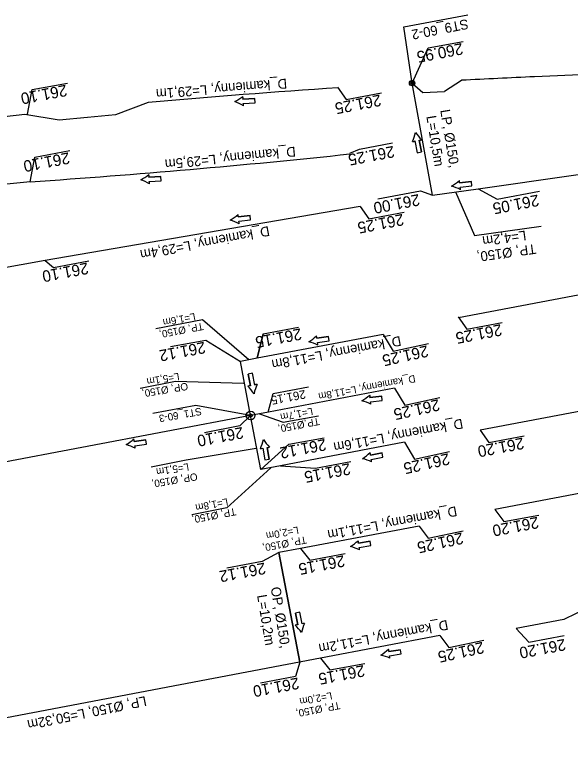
# Model space of a CAD drawing. Extents: x -1 to 65640748, y -22 to 5530284.
# Drawn here: x 6558158.5 to 6558209.5, y 5528782.8 to 5528851.6 of the extents above; entities that cross this region are included whole.
import ezdxf

# ---------------------------------------------------------------- set-up
doc = ezdxf.new("R2010")
doc.units = 0
for name, color, linetype in [('TOR_PROF-studnie i osadniki', 7, 'Continuous'), ('TOR_PS_ODW-drenaze', 7, 'Continuous'), ('TOR_PS_ODW-drenokolektory', 7, 'Continuous'), ('TOR_PS_ODW-kolektory', 7, 'Continuous'), ('TOR_PS_ODW-studnie PEHD', 7, 'Continuous'), ('TOR_PS_OPIS_O-opisy rurociagow', 7, 'Continuous'), ('TOR_PS_OPIS_O-opisy studni', 7, 'Continuous'), ('TOR_PS_OPIS_T-INFO', 7, 'Continuous')]:
    doc.layers.add(name, color=color, linetype=linetype)

msp = doc.modelspace()

# ---------------------------------------------------------------- linework, layer by layer
at = {"layer": 'TOR_PROF-studnie i osadniki'}
for radius in [0.25, 0.125]:
    msp.add_circle((6558194.96, 5528845.381), radius, dxfattribs=at)
at = {"layer": 'TOR_PS_ODW-drenaze'}
for p, q in [((6558170.712, 5528843.594), (6558167.708, 5528842.472)), ((6558162.532, 5528841.974), (6558159.37, 5528842.504)), ((6558165.12, 5528842.223), (6558162.532, 5528841.974)), ((6558167.708, 5528842.472), (6558165.12, 5528842.223)), ((6558192.306, 5528822.298), (6558180.732, 5528820.104)), ((6558240.436, 5528820.938), (6558201.211, 5528813.503)), ((6558193.352, 5528817.357), (6558181.748, 5528815.157)), ((6558242.093, 5528813.721), (6558202.565, 5528806.228)), ((6558194.258, 5528812.389), (6558182.875, 5528810.231)), ((6558197.501, 5528794.632), (6558186.538, 5528792.554))]:
    msp.add_line(p, q, dxfattribs=at)
for points in [[(6558159.37, 5528842.504), (6558140.943, 5528840.386), (6558137.359, 5528840.849), (6558132.205, 5528840.156), (6558124.752, 5528838.168)], [(6558201.038, 5528835.683), (6558235.617, 5528840.624)], [(6558159.869, 5528836.318), (6558159.869, 5528836.318), (6558142.805, 5528834.603)], [(6558196.842, 5528835.084), (6558196.842, 5528835.084), (6558201.038, 5528835.683)], [(6558190.193, 5528834.047), (6558163.214, 5528829.433), (6558161.25, 5528829.08)], [(6558238.341, 5528831.228), (6558199.221, 5528823.813)], [(6558161.25, 5528829.08), (6558127.62, 5528823.039)], [(6558180.732, 5528820.104), (6558179.181, 5528819.811)], [(6558182.875, 5528810.231), (6558181.062, 5528809.887)], [(6558195.594, 5528804.703), (6558184.71, 5528802.64)], [(6558243.69, 5528803.387), (6558211.159, 5528797.221), (6558208.896, 5528796.13), (6558204.51, 5528795.299)], [(6558186.538, 5528792.554), (6558150.243, 5528785.674), (6558147.981, 5528784.584), (6558142.872, 5528783.615), (6558135.31, 5528782.843)]]:
    msp.add_lwpolyline(points, dxfattribs=at)
for centre, radius, start, end in [((6558241.925, 5528042.955), 803.8, 93.834266, 95.082808), ((6558109.688, 5529583.067), 748.433, 273.844417, 276.102336)]:
    msp.add_arc(centre, radius, start, end, dxfattribs=at)
at = {"layer": 'TOR_PS_ODW-drenokolektory'}
for p, q in [((6558235.052, 5528847.244), (6558206.197, 5528845.96)), ((6558199.496, 5528845.63), (6558197.947, 5528844.622)), ((6558194.96, 5528845.381), (6558195.939, 5528844.51)), ((6558195.939, 5528844.51), (6558197.947, 5528844.622)), ((6558180.732, 5528820.104), (6558179.181, 5528819.811)), ((6558180.122, 5528814.849), (6558130.962, 5528805.531)), ((6558181.748, 5528815.157), (6558180.122, 5528814.849)), ((6558182.875, 5528810.231), (6558181.062, 5528809.887))]:
    msp.add_line(p, q, dxfattribs=at)
for points in [[(6558196.842, 5528835.084), (6558194.96, 5528845.381)], [(6558184.71, 5528802.64), (6558182.719, 5528802.262)]]:
    msp.add_lwpolyline(points, dxfattribs=at)
msp.add_arc((6558241.925, 5528042.955), 803.8, 92.547544, 93.025826, dxfattribs=at)
at = {"layer": 'TOR_PS_ODW-kolektory'}
for p, q in [((6558180.122, 5528814.849), (6558179.181, 5528819.811)), ((6558181.062, 5528809.887), (6558180.122, 5528814.849))]:
    msp.add_line(p, q, dxfattribs=at)
for points in [[(6558182.719, 5528802.262), (6558184.628, 5528792.192)], [(6558184.628, 5528792.192), (6558182.719, 5528802.262)]]:
    msp.add_lwpolyline(points, dxfattribs=at)
at = {"layer": 'TOR_PS_ODW-studnie PEHD'}
for centre, radius in [((6558194.96, 5528845.381), 0.25), ((6558194.96, 5528845.381), 0.112), ((6558180.122, 5528814.849), 0.4), ((6558180.122, 5528814.849), 0.145)]:
    msp.add_circle(centre, radius, dxfattribs=at)
at = {"layer": 'TOR_PS_OPIS_O-opisy rurociagow'}
for p, q in [((6558180.505, 5528843.974), (6558179.414, 5528843.916)), ((6558179.414, 5528843.916), (6558180.505, 5528843.974)), ((6558179.435, 5528843.517), (6558180.527, 5528843.575)), ((6558179.435, 5528843.517), (6558180.527, 5528843.575)), ((6558180.527, 5528843.575), (6558180.505, 5528843.974)), ((6558180.527, 5528843.575), (6558180.505, 5528843.974)), ((6558195.814, 5528839.063), (6558195.611, 5528840.136)), ((6558195.611, 5528840.136), (6558195.814, 5528839.063)), ((6558195.218, 5528840.062), (6558195.421, 5528838.988)), ((6558195.218, 5528840.062), (6558195.421, 5528838.988)), ((6558195.421, 5528838.988), (6558195.814, 5528839.063)), ((6558195.421, 5528838.988), (6558195.814, 5528839.063)), ((6558171.874, 5528836.806), (6558170.783, 5528836.747)), ((6558170.783, 5528836.747), (6558171.874, 5528836.806)), ((6558171.895, 5528836.406), (6558171.874, 5528836.806)), ((6558171.895, 5528836.406), (6558171.874, 5528836.806)), ((6558170.804, 5528836.348), (6558171.895, 5528836.406)), ((6558170.804, 5528836.348), (6558171.895, 5528836.406)), ((6558200.404, 5528836.35), (6558199.321, 5528836.209)), ((6558199.321, 5528836.209), (6558200.404, 5528836.35)), ((6558199.373, 5528835.812), (6558200.456, 5528835.954)), ((6558199.373, 5528835.812), (6558200.456, 5528835.954)), ((6558200.456, 5528835.954), (6558200.404, 5528836.35)), ((6558200.456, 5528835.954), (6558200.404, 5528836.35)), ((6558180.069, 5528833.226), (6558178.985, 5528833.084)), ((6558178.985, 5528833.084), (6558180.069, 5528833.226)), ((6558180.12, 5528832.829), (6558180.069, 5528833.226)), ((6558180.12, 5528832.829), (6558180.069, 5528833.226)), ((6558179.037, 5528832.688), (6558180.12, 5528832.829)), ((6558179.037, 5528832.688), (6558180.12, 5528832.829)), ((6558187.267, 5528822.118), (6558186.189, 5528821.939)), ((6558186.189, 5528821.939), (6558187.267, 5528822.118)), ((6558186.255, 5528821.545), (6558187.333, 5528821.723)), ((6558186.255, 5528821.545), (6558187.333, 5528821.723)), ((6558187.333, 5528821.723), (6558187.267, 5528822.118)), ((6558187.333, 5528821.723), (6558187.267, 5528822.118)), ((6558180.293, 5528818.726), (6558179.899, 5528818.653)), ((6558180.293, 5528818.726), (6558179.899, 5528818.653)), ((6558179.899, 5528818.653), (6558180.099, 5528817.579)), ((6558180.099, 5528817.579), (6558179.899, 5528818.653)), ((6558180.492, 5528817.652), (6558180.293, 5528818.726)), ((6558180.492, 5528817.652), (6558180.293, 5528818.726)), ((6558192.169, 5528816.641), (6558191.085, 5528816.504)), ((6558191.085, 5528816.504), (6558192.169, 5528816.641)), ((6558191.135, 5528816.107), (6558192.219, 5528816.244)), ((6558191.135, 5528816.107), (6558192.219, 5528816.244)), ((6558192.219, 5528816.244), (6558192.169, 5528816.641)), ((6558192.219, 5528816.244), (6558192.169, 5528816.641)), ((6558170.504, 5528812.609), (6558169.42, 5528812.472)), ((6558169.42, 5528812.472), (6558170.504, 5528812.609)), ((6558170.554, 5528812.212), (6558170.504, 5528812.609)), ((6558170.554, 5528812.212), (6558170.504, 5528812.609)), ((6558169.47, 5528812.075), (6558170.554, 5528812.212)), ((6558169.47, 5528812.075), (6558170.554, 5528812.212)), ((6558181.829, 5528810.847), (6558181.629, 5528811.921)), ((6558181.629, 5528811.921), (6558181.829, 5528810.847)), ((6558181.236, 5528811.848), (6558181.436, 5528810.774)), ((6558181.236, 5528811.848), (6558181.436, 5528810.774)), ((6558192.195, 5528811.409), (6558191.12, 5528811.217)), ((6558191.12, 5528811.217), (6558192.195, 5528811.409)), ((6558192.266, 5528811.015), (6558192.195, 5528811.409)), ((6558192.266, 5528811.015), (6558192.195, 5528811.409)), ((6558181.436, 5528810.774), (6558181.829, 5528810.847)), ((6558181.436, 5528810.774), (6558181.829, 5528810.847)), ((6558191.19, 5528810.823), (6558192.266, 5528811.015)), ((6558191.19, 5528810.823), (6558192.266, 5528811.015)), ((6558191.095, 5528803.304), (6558190.016, 5528803.131)), ((6558190.016, 5528803.131), (6558191.095, 5528803.304)), ((6558191.158, 5528802.909), (6558191.095, 5528803.304)), ((6558191.158, 5528802.909), (6558191.095, 5528803.304)), ((6558190.079, 5528802.736), (6558191.158, 5528802.909)), ((6558190.079, 5528802.736), (6558191.158, 5528802.909)), ((6558184.645, 5528796.78), (6558184.251, 5528796.707)), ((6558184.645, 5528796.78), (6558184.251, 5528796.707)), ((6558184.844, 5528795.705), (6558184.645, 5528796.78)), ((6558184.844, 5528795.705), (6558184.645, 5528796.78)), ((6558184.251, 5528796.707), (6558184.451, 5528795.632)), ((6558184.451, 5528795.632), (6558184.251, 5528796.707)), ((6558193.886, 5528793.345), (6558192.807, 5528793.172)), ((6558192.807, 5528793.172), (6558193.886, 5528793.345)), ((6558193.949, 5528792.95), (6558193.886, 5528793.345)), ((6558193.949, 5528792.95), (6558193.886, 5528793.345)), ((6558192.87, 5528792.777), (6558193.949, 5528792.95)), ((6558192.87, 5528792.777), (6558193.949, 5528792.95))]:
    msp.add_line(p, q, dxfattribs=at)
for points in [[(6558179.412, 5528844.141), (6558179.412, 5528844.141)], [(6558179.458, 5528843.293), (6558179.458, 5528843.293)], [(6558195.834, 5528840.168), (6558195.834, 5528840.168)], [(6558194.999, 5528840.01), (6558194.999, 5528840.01)], [(6558170.781, 5528836.972), (6558170.781, 5528836.972)], [(6558170.826, 5528836.124), (6558170.826, 5528836.124)], [(6558199.302, 5528836.433), (6558199.302, 5528836.433)], [(6558199.412, 5528835.591), (6558199.412, 5528835.591)], [(6558178.966, 5528833.309), (6558178.966, 5528833.309)], [(6558179.076, 5528832.466), (6558179.076, 5528832.466)], [(6558186.163, 5528822.163), (6558186.163, 5528822.163)], [(6558186.302, 5528821.324), (6558186.302, 5528821.325)], [(6558179.876, 5528817.548), (6558179.876, 5528817.548)], [(6558180.711, 5528817.703), (6558180.711, 5528817.703)], [(6558191.067, 5528816.729), (6558191.067, 5528816.729)], [(6558191.173, 5528815.886), (6558191.173, 5528815.886)], [(6558169.402, 5528812.696), (6558169.402, 5528812.696)], [(6558181.852, 5528811.952), (6558181.852, 5528811.952)], [(6558169.509, 5528811.853), (6558169.509, 5528811.853)], [(6558181.017, 5528811.797), (6558181.017, 5528811.797)], [(6558191.09, 5528811.44), (6558191.09, 5528811.44)], [(6558191.239, 5528810.604), (6558191.239, 5528810.604)], [(6558189.99, 5528803.355), (6558189.99, 5528803.355)], [(6558190.125, 5528802.516), (6558190.125, 5528802.516)], [(6558184.228, 5528795.601), (6558184.228, 5528795.601)], [(6558185.063, 5528795.757), (6558185.063, 5528795.757)], [(6558192.782, 5528793.396), (6558192.782, 5528793.396)], [(6558192.916, 5528792.557), (6558192.916, 5528792.557)]]:
    msp.add_lwpolyline(points, dxfattribs=at)
for centre, radius, start, end in [((6558176.469, 5528848.081), 4.918, 296.3889, 306.77073), ((6558176.469, 5528848.081), 4.918, 296.3889, 306.77073), ((6558176.951, 5528839.062), 4.918, 59.35101, 69.73284), ((6558176.951, 5528839.062), 4.918, 59.35101, 69.73284), ((6558178.969, 5528844.025), 0.458, 346.19493, 14.65617), ((6558178.969, 5528844.025), 0.458, 346.19493, 14.65617), ((6558179.005, 5528843.361), 0.458, 351.46558, 19.92682), ((6558179.005, 5528843.361), 0.458, 351.46558, 19.92682), ((6558190.471, 5528841.93), 4.918, 337.02338, 347.40521), ((6558190.471, 5528841.93), 4.918, 337.02338, 347.40521), ((6558199.345, 5528843.612), 4.918, 214.06127, 224.4431), ((6558199.345, 5528843.612), 4.918, 214.06127, 224.4431), ((6558195.66, 5528840.592), 0.458, 263.86729, 292.32853), ((6558195.66, 5528840.592), 0.458, 263.86729, 292.32853), ((6558195.006, 5528840.468), 0.458, 269.13794, 297.59919), ((6558195.006, 5528840.468), 0.458, 269.13794, 297.59919), ((6558167.837, 5528840.912), 4.918, 296.3889, 306.77073), ((6558167.837, 5528840.912), 4.918, 296.3889, 306.77073), ((6558170.338, 5528836.856), 0.458, 346.19493, 14.65617), ((6558170.338, 5528836.856), 0.458, 346.19493, 14.65617), ((6558168.319, 5528831.893), 4.918, 59.35101, 69.73284), ((6558168.319, 5528831.893), 4.918, 59.35101, 69.73284), ((6558170.374, 5528836.192), 0.458, 351.46558, 19.92682), ((6558170.374, 5528836.192), 0.458, 351.46558, 19.92682), ((6558196.066, 5528840.137), 4.918, 300.76623, 311.14806), ((6558196.066, 5528840.137), 4.918, 300.76623, 311.14806), ((6558198.869, 5528836.284), 0.458, 350.57226, 19.0335), ((6558198.869, 5528836.284), 0.458, 350.57226, 19.0335), ((6558197.235, 5528831.181), 4.918, 63.72835, 74.11017), ((6558197.235, 5528831.181), 4.918, 63.72835, 74.11017), ((6558198.955, 5528835.624), 0.458, 355.84291, 24.30415), ((6558198.955, 5528835.624), 0.458, 355.84291, 24.30415), ((6558175.73, 5528837.012), 4.918, 300.76623, 311.14806), ((6558175.73, 5528837.012), 4.918, 300.76623, 311.14806), ((6558178.533, 5528833.159), 0.458, 350.57226, 19.0335), ((6558178.533, 5528833.159), 0.458, 350.57226, 19.0335), ((6558176.899, 5528828.056), 4.918, 63.72835, 74.11017), ((6558176.899, 5528828.056), 4.918, 63.72835, 74.11017), ((6558178.62, 5528832.499), 0.458, 355.84291, 24.30415), ((6558178.62, 5528832.499), 0.458, 355.84291, 24.30415), ((6558182.802, 5528825.753), 4.918, 302.72798, 313.10981), ((6558182.802, 5528825.753), 4.918, 302.72798, 313.10981), ((6558184.277, 5528816.843), 4.918, 65.69009, 76.07192), ((6558184.277, 5528816.843), 4.918, 65.69009, 76.07192), ((6558185.735, 5528821.999), 0.458, 352.534, 20.99524), ((6558185.735, 5528821.999), 0.458, 352.534, 20.99524), ((6558185.844, 5528821.342), 0.458, 357.80466, 26.2659), ((6558185.844, 5528821.342), 0.458, 357.80466, 26.2659), ((6558180.048, 5528817.124), 0.458, 83.66036, 112.1216), ((6558180.048, 5528817.124), 0.458, 83.66036, 112.1216), ((6558176.352, 5528814.117), 4.918, 33.85434, 44.23617), ((6558176.352, 5528814.117), 4.918, 33.85434, 44.23617), ((6558185.232, 5528815.767), 4.918, 156.81645, 167.19828), ((6558185.232, 5528815.767), 4.918, 156.81645, 167.19828), ((6558180.703, 5528817.245), 0.458, 88.93101, 117.39225), ((6558180.703, 5528817.245), 0.458, 88.93101, 117.39225), ((6558187.846, 5528820.445), 4.918, 300.53119, 310.91302), ((6558187.846, 5528820.445), 4.918, 300.53119, 310.91302), ((6558190.633, 5528816.581), 0.458, 350.33722, 18.79846), ((6558190.633, 5528816.581), 0.458, 350.33722, 18.79846), ((6558188.978, 5528811.485), 4.918, 63.4933, 73.87513), ((6558188.978, 5528811.485), 4.918, 63.4933, 73.87513), ((6558190.717, 5528815.921), 0.458, 355.60787, 24.06911), ((6558190.717, 5528815.921), 0.458, 355.60787, 24.06911), ((6558166.182, 5528816.413), 4.918, 300.53119, 310.91302), ((6558166.182, 5528816.413), 4.918, 300.53119, 310.91302), ((6558168.969, 5528812.549), 0.458, 350.33722, 18.79846), ((6558168.969, 5528812.549), 0.458, 350.33722, 18.79846), ((6558176.496, 5528813.733), 4.918, 336.81645, 347.19828), ((6558176.496, 5528813.733), 4.918, 336.81645, 347.19828), ((6558185.376, 5528815.383), 4.918, 213.85434, 224.23617), ((6558185.376, 5528815.383), 4.918, 213.85434, 224.23617), ((6558167.314, 5528807.453), 4.918, 63.4933, 73.87513), ((6558167.314, 5528807.453), 4.918, 63.4933, 73.87513), ((6558169.052, 5528811.889), 0.458, 355.60787, 24.06911), ((6558169.052, 5528811.889), 0.458, 355.60787, 24.06911), ((6558181.68, 5528812.376), 0.458, 263.66036, 292.1216), ((6558181.68, 5528812.376), 0.458, 263.66036, 292.1216), ((6558181.026, 5528812.254), 0.458, 268.93101, 297.39225), ((6558181.026, 5528812.254), 0.458, 268.93101, 297.39225), ((6558187.686, 5528814.989), 4.918, 303.42506, 313.80689), ((6558187.686, 5528814.989), 4.918, 303.42506, 313.80689), ((6558190.665, 5528811.271), 0.458, 353.23109, 21.69233), ((6558190.665, 5528811.271), 0.458, 353.23109, 21.69233), ((6558189.27, 5528806.098), 4.918, 66.38718, 76.769), ((6558189.27, 5528806.098), 4.918, 66.38718, 76.769), ((6558190.782, 5528810.616), 0.458, 358.50174, 26.96298), ((6558190.782, 5528810.616), 0.458, 358.50174, 26.96298), ((6558186.648, 5528806.962), 4.918, 302.43307, 312.81489), ((6558186.648, 5528806.962), 4.918, 302.43307, 312.81489), ((6558189.562, 5528803.193), 0.458, 352.23909, 20.70033), ((6558189.562, 5528803.193), 0.458, 352.23909, 20.70033), ((6558188.077, 5528798.044), 4.918, 65.39518, 75.77701), ((6558188.077, 5528798.044), 4.918, 65.39518, 75.77701), ((6558189.667, 5528802.536), 0.458, 357.50974, 25.97098), ((6558189.667, 5528802.536), 0.458, 357.50974, 25.97098), ((6558184.4, 5528795.177), 0.458, 83.66036, 112.1216), ((6558184.4, 5528795.177), 0.458, 83.66036, 112.1216), ((6558180.704, 5528792.171), 4.918, 33.85434, 44.23617), ((6558180.704, 5528792.171), 4.918, 33.85434, 44.23617), ((6558189.584, 5528793.821), 4.918, 156.81645, 167.19828), ((6558189.584, 5528793.821), 4.918, 156.81645, 167.19828), ((6558185.055, 5528795.299), 0.458, 88.93101, 117.39225), ((6558185.055, 5528795.299), 0.458, 88.93101, 117.39225), ((6558189.439, 5528797.003), 4.918, 302.43307, 312.81489), ((6558189.439, 5528797.003), 4.918, 302.43307, 312.81489), ((6558192.353, 5528793.234), 0.458, 352.23909, 20.70033), ((6558192.353, 5528793.234), 0.458, 352.23909, 20.70033), ((6558190.868, 5528788.085), 4.918, 65.39518, 75.77701), ((6558190.868, 5528788.085), 4.918, 65.39518, 75.77701), ((6558192.459, 5528792.576), 0.458, 357.50974, 25.97098), ((6558192.459, 5528792.576), 0.458, 357.50974, 25.97098)]:
    msp.add_arc(centre, radius, start, end, dxfattribs=at)
at = {"layer": 'TOR_PS_OPIS_T-INFO'}
for points in [[(6558194.96, 5528845.381), (6558194.189, 5528850.538), (6558200.083, 5528851.636)], [(6558194.96, 5528845.381), (6558196.418, 5528848.609), (6558199.655, 5528849.211)], [(6558159.625, 5528842.53), (6558160.044, 5528844.785), (6558163.281, 5528845.387)], [(6558188.092, 5528845.009), (6558188.901, 5528843.885), (6558192.138, 5528844.487)], [(6558189.243, 5528838.937), (6558190.136, 5528839.306), (6558193.145, 5528839.894)], [(6558159.869, 5528836.318), (6558160.288, 5528838.572), (6558163.525, 5528839.175)], [(6558191.809, 5528834.763), (6558191.809, 5528834.763), (6558195.716, 5528835.49), (6558196.842, 5528835.084)], [(6558198.94, 5528835.383), (6558200.687, 5528831.39), (6558206.814, 5528832.239)], [(6558201.038, 5528835.683), (6558202.758, 5528834.716), (6558206.666, 5528835.443)], [(6558190.171, 5528834.043), (6558190.98, 5528832.918), (6558194.217, 5528833.521)], [(6558161.25, 5528829.08), (6558162.012, 5528828.452), (6558165.249, 5528829.055)], [(6558179.956, 5528819.958), (6558175.702, 5528823.649), (6558171.417, 5528822.822)], [(6558199.183, 5528823.915), (6558199.991, 5528822.79), (6558203.229, 5528823.393)], [(6558181.27, 5528822.349), (6558180.732, 5528820.104), (6558181.27, 5528822.349), (6558184.508, 5528822.951), (6558184.508, 5528822.951)], [(6558192.306, 5528822.298), (6558193.231, 5528820.756), (6558196.449, 5528821.452)], [(6558172.768, 5528821.175), (6558172.768, 5528821.175), (6558176.006, 5528821.778), (6558179.181, 5528819.811)], [(6558179.471, 5528817.785), (6558173.217, 5528817.96), (6558169.984, 5528817.336)], [(6558181.73, 5528815.154), (6558182.188, 5528816.871), (6558185.425, 5528817.474)], [(6558193.352, 5528817.357), (6558194.276, 5528815.814), (6558197.495, 5528816.51)], [(6558180.122, 5528814.849), (6558175.084, 5528815.78), (6558171.151, 5528815.021)], [(6558180.122, 5528814.849), (6558179.126, 5528813.897), (6558175.893, 5528813.273)], [(6558180.935, 5528815.003), (6558183.125, 5528814.23), (6558186.362, 5528814.833)], [(6558201.211, 5528813.503), (6558202.02, 5528812.378), (6558205.257, 5528812.981)], [(6558181.062, 5528809.887), (6558183.633, 5528812.207), (6558186.871, 5528812.809)], [(6558194.258, 5528812.389), (6558195.183, 5528810.846), (6558198.401, 5528811.542)], [(6558180.636, 5528811.826), (6558174.206, 5528810.744), (6558170.972, 5528810.12)], [(6558182.875, 5528810.231), (6558186.086, 5528810.024), (6558189.323, 5528810.626)], [(6558181.968, 5528810.059), (6558177.946, 5528806.364), (6558174.713, 5528805.74)], [(6558202.565, 5528806.228), (6558203.374, 5528805.103), (6558206.611, 5528805.706)], [(6558195.597, 5528804.675), (6558196.438, 5528803.574), (6558199.657, 5528804.27)], [(6558182.719, 5528802.262), (6558181.17, 5528801.44), (6558177.936, 5528800.817)], [(6558184.71, 5528802.64), (6558185.556, 5528801.57), (6558188.793, 5528802.173)], [(6558204.51, 5528795.299), (6558205.68, 5528794.042), (6558208.918, 5528794.645)], [(6558197.501, 5528794.632), (6558198.342, 5528793.531), (6558201.56, 5528794.228)], [(6558184.642, 5528792.195), (6558184.246, 5528790.889), (6558181.013, 5528790.265)], [(6558186.538, 5528792.554), (6558187.384, 5528791.484), (6558190.622, 5528792.087)]]:
    msp.add_lwpolyline(points, dxfattribs=at)

# ---------------------------------------------------------------- texts
at = {"layer": 'TOR_PS_OPIS_O-opisy rurociagow'}
for s, height, rotation, p in [('D_kamienny, L=29,1m', 0.9, 184.58898, (6558183.428, 5528845.792)), ('LP, Ø150, ', 0.9, 279.43093, (6558197.535, 5528842.891)), ('L=10,5m', 0.9, 279.43093, (6558196.261, 5528842.324)), ('D_kamienny, L=29,5m', 0.9, 185.64977, (6558184.218, 5528839.545)), ('D_kamienny, L=29,4m', 0.9, 190.59848, (6558181.772, 5528832.253)), ('L=4,2m', 0.9, 187.91927, (6558205.371, 5528831.843)), ('TP, Ø150, ', 0.9, 187.91927, (6558206.285, 5528830.608)), ('L=1,6m', 0.675, 190.73324, (6558174.987, 5528824.273)), ('TP, Ø150, ', 0.675, 190.73324, (6558175.718, 5528823.381)), ('D_kamienny, L=11,8m', 0.9, 190.59848, (6558193.859, 5528822.16)), ('L=5,1m', 0.675, 189.43093, (6558173.518, 5528818.775)), ('D_kamienny, L=11,8m', 0.675, 190.59848, (6558195.196, 5528818.58)), ('OP, Ø150, ', 0.675, 189.43093, (6558174.305, 5528817.879)), ('L=1,7m', 0.675, 190.73324, (6558185.779, 5528815.574)), ('TP,Ø150, ', 0.675, 190.73324, (6558186.381, 5528814.657)), ('D_kamienny, L=11,6m', 0.9, 190.59848, (6558199.543, 5528814.566)), ('L=5,1m', 0.675, 189.43093, (6558174.395, 5528810.476)), ('OP, Ø150, ', 0.675, 189.43093, (6558175.183, 5528809.58)), ('L=1,8m', 0.675, 190.73324, (6558177.98, 5528807.259)), ('D_kamienny, L=11,1m', 0.9, 190.59848, (6558198.99, 5528806.522)), ('TP, Ø150, ', 0.675, 190.73324, (6558178.71, 5528806.367)), ('L=2,0m', 0.675, 190.73324, (6558184.469, 5528804.666)), ('TP, Ø150,', 0.675, 190.73324, (6558185.2, 5528803.774)), ('OP, Ø150,', 0.9, 279.43093, (6558181.96, 5528799.036)), ('L=10,2m', 0.9, 279.43093, (6558180.709, 5528798.331)), ('D_kamienny, L=11,2m', 0.9, 190.59848, (6558198.177, 5528796.079)), ('L=2,0m', 0.675, 190.73324, (6558187.545, 5528789.457)), ('LP, Ø150, L=50,32m', 0.9, 191.56565, (6558170.45, 5528789.088)), ('TP, Ø150,', 0.675, 190.73324, (6558188.275, 5528788.565))]:
    msp.add_text(s, height=height, rotation=rotation, dxfattribs=at).set_placement(p)
at = {"layer": 'TOR_PS_OPIS_O-opisy studni'}
for s, height, rotation, p in [('ST9_60-2', 0.9, 191.11395, (6558200.032, 5528851.266)), ('ST1_60-3', 0.675, 190.11405, (6558175.558, 5528815.578))]:
    msp.add_text(s, height=height, rotation=rotation, dxfattribs=at).set_placement(p)
at = {"layer": 'TOR_PS_OPIS_T-INFO'}
for s, height, rotation, p in [('260.95', 1.05, 190.75061, (6558199.528, 5528849.068)), ('261.10', 1.05, 190.75061, (6558163.151, 5528845.243)), ('261.25', 1.05, 190.75061, (6558192.011, 5528844.343)), ('261.25', 1.05, 190.75061, (6558193.232, 5528839.623)), ('261.10', 1.05, 190.75061, (6558163.395, 5528839.03)), ('261.00', 1.05, 190.75061, (6558195.554, 5528835.196)), ('261.05', 1.05, 190.75061, (6558206.507, 5528835.15)), ('261.25', 1.05, 190.75061, (6558194.09, 5528833.377)), ('261.10', 1.05, 190.75061, (6558165.119, 5528828.911)), ('261.25', 1.05, 190.75061, (6558203.102, 5528823.249)), ('261.15', 1.05, 190.75061, (6558184.7, 5528822.867)), ('261.12', 1.05, 190.75061, (6558175.872, 5528821.632)), ('261.25', 1.05, 192.41745, (6558196.327, 5528821.305)), ('261.15', 0.7875, 190.75061, (6558185.098, 5528817.204)), ('261.25', 1.05, 192.41745, (6558197.372, 5528816.363)), ('261.10', 1.05, 190.71587, (6558179.358, 5528813.809)), ('261.12', 1.05, 190.75061, (6558186.959, 5528812.706)), ('261.20', 1.05, 190.75061, (6558205.127, 5528812.836)), ('261.25', 1.05, 192.41745, (6558198.278, 5528811.395)), ('261.15', 1.05, 190.75061, (6558189.196, 5528810.483)), ('261.20', 1.05, 190.75061, (6558206.481, 5528805.561)), ('261.25', 1.05, 192.41745, (6558199.534, 5528804.123)), ('261.15', 1.05, 190.75061, (6558188.666, 5528802.029)), ('261.12', 1.05, 190.71587, (6558181.397, 5528801.352)), ('261.25', 1.05, 192.41745, (6558201.438, 5528794.08)), ('261.20', 1.05, 190.75061, (6558208.957, 5528794.344)), ('261.15', 1.05, 190.75061, (6558190.495, 5528791.943)), ('261.10', 1.05, 190.71587, (6558184.478, 5528790.801))]:
    msp.add_text(s, height=height, rotation=rotation, dxfattribs=at).set_placement(p)

doc.saveas('drawing.dxf')
